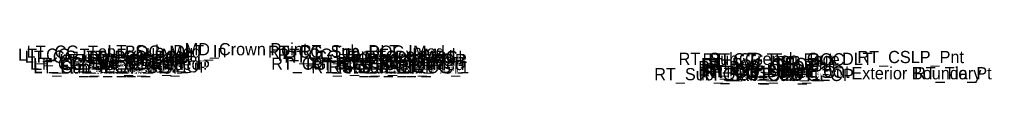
# Model space of a CAD drawing. Extents: x -26 to 6300, y -10 to 9528.
# Drawn here: x 2126 to 2206, y 5518.4 to 5521.9 of the extents above; entities that cross this region are included whole.
import ezdxf

# ---------------------------------------------------------------- set-up
doc = ezdxf.new("R2010")
doc.units = 0
doc.layers.add('Default', color=7, linetype='Continuous')

msp = doc.modelspace()

# ---------------------------------------------------------------- texts
at = {"layer": 'Default'}
for s, p in [('MD_Crown Point', (2139.582, 5520.832)), ('LT_CG_Top_Face_Med', (2125.866, 5520.382)), ('LT_CG_Top_Gut_Med', (2126.418, 5520.216)), ('LT_CG_Top_BOC_Med', (2126.569, 5520.632)), ('LT_PV1_PGL', (2131.503, 5520.201)), ('LT_Sub_DLT_In', (2133.217, 5520.672)), ('RT_CG_Top_BOC_Med', (2146.431, 5520.632)), ('RT_CG_Top_Face_Med', (2147.246, 5520.382)), ('RT_CG_Top_Gut_Med', (2147.8, 5520.216)), ('RT_Sub_DLT_In', (2149.068, 5520.672)), ('RT_PV1_PGL', (2154.385, 5520.201)), ('RT_Sub_Trench_Out_DLT', (2180.257, 5520.042)), ('RT_CG_Top_Face', (2182.225, 5520.001)), ('RT_CG_Top_BOC', (2182.694, 5520.001)), ('RT_CSLP_Pnt', (2194.982, 5520.191)), ('LT_CG_Bot_BOC_Med', (2126.846, 5519.648)), ('LT_CG_Bot_IE_Med', (2127.094, 5519.617)), ('LT_Sub_IEOT_CG_1', (2127.125, 5519.367)), ('LT_PV2_OEEOP', (2129.285, 5519.951)), ('LT_PV3_OEEOP', (2129.285, 5519.701)), ('LT_Sub_OEEOP', (2129.332, 5519.326)), ('LT_PV2_IEEOP', (2130.046, 5519.951)), ('LT_Sub_IEEOP', (2130.093, 5519.326)), ('LT_CG1_Shelf_In', (2130.712, 5519.658)), ('LT_PV2_PGL', (2131.264, 5519.951)), ('LT_Sub_PGL', (2131.311, 5519.326)), ('LT_Sub_IEOP', (2133.045, 5519.412)), ('RT_CG_Bot_BOC_Med', (2146.708, 5519.648)), ('RT_CG1_Shelf_In', (2149.573, 5519.658)), ('RT_CG_Bot_IE_Med', (2149.976, 5519.617)), ('RT_Sub_IEOT_CG_1', (2150.007, 5519.367)), ('RT_Sub_IEOP', (2151.417, 5519.412)), ('RT_PV2_OEEOP', (2152.167, 5519.951)), ('RT_PV3_OEEOP', (2152.167, 5519.701)), ('RT_Sub_OEEOP', (2152.214, 5519.326)), ('RT_PV2_IEEOP', (2152.928, 5519.951)), ('RT_Sub_IEEOP', (2152.975, 5519.326)), ('RT_PV2_PGL', (2154.145, 5519.951)), ('RT_Sub_PGL', (2154.192, 5519.326)), ('RT_PV2_OEOT', (2181.873, 5519.371)), ('RT_PV1_OEOT', (2182.112, 5519.621)), ('RT_CG_Top_Gut', (2182.752, 5519.501)), ('RT_Sub_OEOT_CG_1', (2178.247, 5518.787)), ('RT_PV3_OEOT', (2181.873, 5519.121)), ('RT_Sub_OEOT', (2181.92, 5518.746)), ('RT_CG_Bot_IE', (2182.221, 5519.037)), ('RT_CG1_Shelf_Out', (2182.36, 5518.977)), ('RT_CG_Bot_BOC', (2182.97, 5518.987)), ('RT_Sub_OEOP', (2185.166, 5518.722)), ('Exterior Boundary', (2194.481, 5518.861)), ('RT_Tie_Pt', (2199.643, 5518.861))]:
    msp.add_text(s, height=1, dxfattribs=at).set_placement(p)

doc.saveas('drawing.dxf')
